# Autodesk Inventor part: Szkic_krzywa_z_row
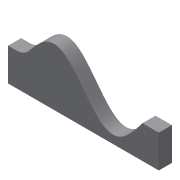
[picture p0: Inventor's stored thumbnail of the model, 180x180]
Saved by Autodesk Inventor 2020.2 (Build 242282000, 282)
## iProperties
Created: 2013-12
Part Number: Szkic_krzywa_z_row
Material: Ogólny
Document SubType Name: Modeling
Designer: F.Stasiak
Density: 1 g/cm^3
Appearance: Domyślna
Manager: www.cadconsulting.pl
Company: Fabian Stasiak CAD Consulting
Author: F.Stasiak
Subject: Zbiór ćwiczeń. Autodesk Inventor 2020. Kurs podstawowy
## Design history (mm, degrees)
sketch "Szkic1"
  geometry: L1 (180, 0)-(180, 0); L2 (0, 0)-(-50, 0); L3 (-50, 0)-(-50, -100); L4 (-50, -100)-(410, -100); L5 (410, -100)-(410, 0); L6 (410, 0)-(360, 0)
  constraints: 12 end point, 3 parallel, 1 collinear, 1 horizontal, 1 perpendicular, 4 other
  dimensions: "d9" = 50 distance of L2.start L2.end; "d10" = 100 distance of L2.end L3.end; "d11" = 460 distance of L3.end L4.end
extrude "Wyciągnięcie proste1" new body sketch "Szkic1" distance "d13" = 40; taper "d14" = 0 deg
fillet "Zaokrąglenie1" dims "d15" = 50
node "Bryła1"
node "Krzywa z równania 2D3" dims "d6" = 0, "d7" = 3600
